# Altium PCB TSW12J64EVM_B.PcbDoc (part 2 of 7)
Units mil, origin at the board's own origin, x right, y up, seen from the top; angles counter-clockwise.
Board outline 8833 x 2680 mil, 10 copper layers (Top Layer L1, Gnd-Plane - L2, Signals - L3, Gnd-Plane - L4, Pwr Plane - L5, Signals - L6, Gnd-Plane - L7, Signals - L8, Gnd-Plane - L9, Bottom Layer - L10), stack 57.8 mil thick; 950 components, 533 nets, 2888 pads, 1732 vias.
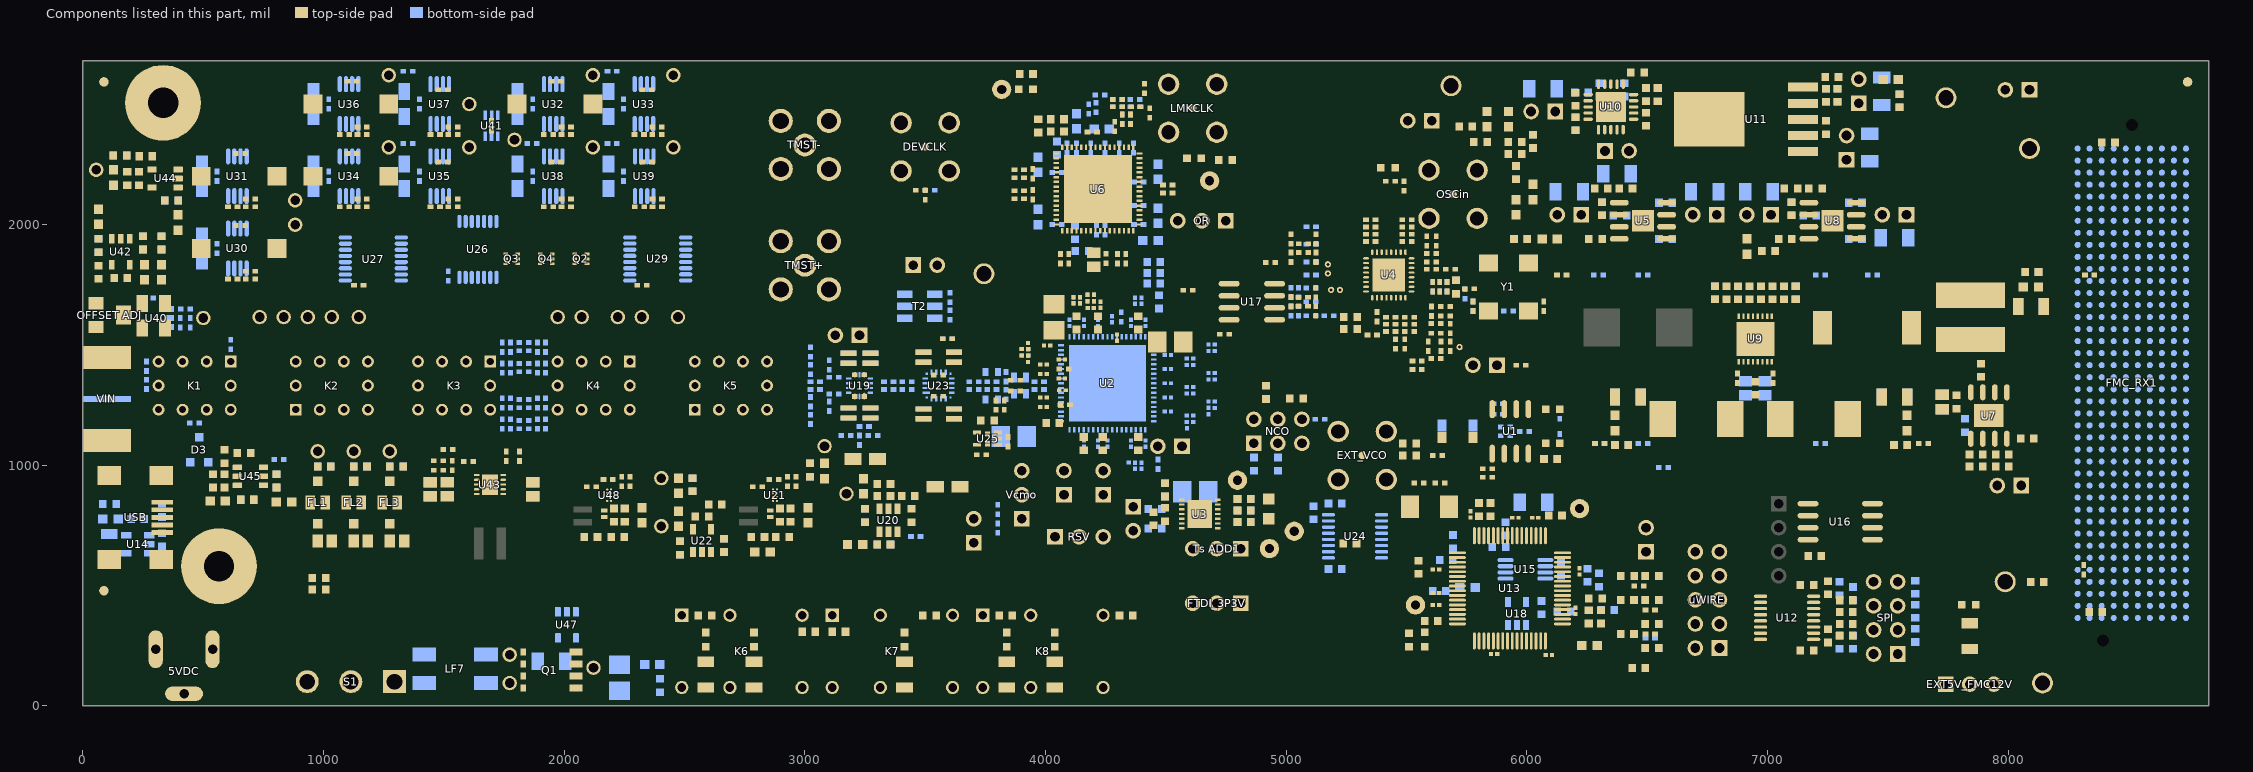
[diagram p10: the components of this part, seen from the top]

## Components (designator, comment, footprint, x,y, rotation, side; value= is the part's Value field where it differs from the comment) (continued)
R85 "CRCW06032K49FKEA" 0603L#1 6202.68,2520 r270 top
R86 "CRCW06035K90FKEA" 0603L#1 7069,1716 r270 top
R87 "CRCW06035K90FKEA" 0603L#1 6829,1716 r270 top
R88 "CRCW06034K99FKEA" 0603L#1 6226.68,2547.56 r180 bottom
R89 "CRCW06032K80FKEA" 0603L#1 6404.36,2558.87 r90 bottom
R90 "RC0603FR-07402RL" 0603L#1 6494.68,2539 r90 bottom
R91 "CRCW04024K99FKED" 0402L#1 5681.98,1567 r270 top
R92 "CSNL1206FT2L00" 1206 7474.44,2552.93 r90 bottom
R93 "RC0603FR-071KL" 0603L#1 7243,2536.39 r270 bottom
R94 "CRCW12061K00JNEA" 1206L 7840,289 r270 top
R95 "CSNL1206FT2L00" 1206 7423.44,2319.07 r90 bottom
R96 "RC0603FR-07357RL" 0603L#1 7267,2612 r180 top
R97 "CRCW060312K4FKEA" 0603L#1 6520,540 r0 top
R98 "CRCW060312K4FKEA" 0603L#1 6520,440 r0 top
R99 "ERJ-3GEY0R00V" 0603L#1 4455,737 r0 bottom
R100 "ERJ-3GEY0R00V" 0603L#1 4455,817 r0 bottom
R101 "CRCW060312K4FKEA" 0603L#1 6520,340 r0 top
R102 "CRCW060312K4FKEA" 0603L#1 6520,240 r0 top
R103 "CRCW06030000Z0EA" 0603L#1 329.24,811.96 r270 bottom
R104 "CRCW040224K0JNED" 0402L#1 6512.13,398 r180 top
R105 "CRCW060310K0FKEA" 0603L#1 5911.32,735 r90 bottom
R106 "CRCW060310K0FKEA" 0603L#1 5848.2,815 r90 top
R107 "CRCW060310K0FKEA" 0603L#1 5800.2,815 r90 top
R108 "RC0603JR-072K2L" 0603L#1 5883.76,659 r0 bottom
R109 "CRCW0603100RJNEA" 0603L#1 7327,438.5 r180 top
R110 "CRCW0603100RJNEA" 0603L#1 7327,340.5 r180 top
R111 "CRCW0603100RJNEA" 0603L#1 7327,389.5 r180 top
R112 "CRCW0603270RJNEA" 0603L#1 5510.91,273.24 r270 top
R113 "CRCW0603100RJNEA" 0603L#1 6418,540 r180 top
R114 "CRCW0603100RJNEA" 0603L#1 6417.44,298 r180 top
R115 "CRCW0603100RJNEA" 0603L#1 6464.88,157.56 r180 top
R116 "CRCW040224K0JNED" 0402L#1 6465.24,498 r180 top
R117 "CRCW0603100RJNEA" 0603L#1 6154.26,392.13 r180 bottom
R118 "CRCW0603100RJNEA" 0603L#1 7327,291.5 r180 top
R119 "CRCW0603100RJNEA" 0603L#1 6520,540 r0 bottom
R120 "CRCW0603100RJNEA" 0603L#1 6520,340 r0 bottom
R121 "CRCW0603100RJNEA" 0603L#1 6520,240 r0 bottom
R122 "RC0603JR-071K3L" 0603L#1 4122.93,1966.24 r270 bottom
R123 "CRCW060310K0FKEA" 0603L#1 7251,290.53 r270 top
R124 "CRCW0603100RJNEA" 0603L#1 6257,369.57 r270 top
R125 "CRCW0603100RJNEA" 0603L#1 6308.56,369.57 r270 top
R126 "CRCW0603100RJNEA" 0603L#1 6285,445 r0 top
R127 "CRCW0603100RJNEA" 0603L#1 6336.12,397.13 r0 bottom
R128 "CRCW040224K0JNED" 0402L#1 6512.13,298 r180 top
R129 "CRCW040224K0JNED" 0402L#1 6512.13,282 r180 bottom
R130 "CRCW060310K0FKEA" 0603L#1 6300,522.46 r270 bottom
R131 "CRCW060310K0FKEA" 0603L#1 6251,542.15 r270 bottom
R132 "CRCW06030000Z0EA" 0603L#1 8120,515 r0 top
R133 "CRCW04021K00FKED" 0402L#1 5923.24,1640 r180 bottom
R134 "RC0603JR-071KL" 0603L#1 4450,1754 r180 bottom
R135 "CRCW06032K10FKEA" 0603L#1 4470.64,1678.24 r90 bottom
R136 "CRCW06034K70JNEA" 0603L#1 4915.5,1302 r90 top
R137 "CRCW06034K70JNEA" 0603L#1 5043.06,1276 r0 top
R138 "CRCW06034K70JNEA" 0603L#1 5512.5,1040 r0 top
R139 "CRCW06032K00JNEA" 0603L#1 7613.44,292.56 r270 bottom
R140 "CRCW06032K00JNEA" 0603L#1 7613.44,392.56 r270 bottom
R141 "CRCW06032K00JNEA" 0603L#1 7613.44,492.56 r270 bottom
R142 "ERJ-3GEY0R00V" 0603L#1 4450,1843 r180 bottom
R143 "ERJ-3GEY0R00V" 0603L#1 4450,1798.5 r180 bottom
R144 "CRCW040210K0FKED" 0402L#5 5622.92,1588 r0 top
R145 "ERJ-2GE0R00X" 0402L#6 5603.24,1639 r270 top
R146 "ERJ-2GE0R00X" 0402L#1 5544,1432.5 r0 top
R147 "ERJ-2GE0R00X" 0402L#1 5544,1397.5 r180 top
R148 "ERJ-2GE0R00X" 0402L#6 5642.61,1494 r270 top
R149 "ERJ-2GE0R00X" 0402L#5 5590.24,1494 r90 top
R150 "CRCW04021M00JNED" 0402L#1 5681.98,1494 r90 top
R151 "CRCW06030000Z0EA" 0603L#1 5267,1615 r0 top
R152 "CRCW06030000Z0EA" 0603L#1 5267,1565 r180 top
R153 "CRCW040249R9FKED" 0402L#1 5357.34,1540 r0 top
R154 "CRCW0402261RFKED" 0402L#1 5489,2159.68 r270 top
R156 "CRCW0402127RFKED" 0402L#1 4372.35,2519 r0 bottom
R157 "CRCW0402127RFKED" 0402L#1 4298.98,2519 r180 bottom
R158 "CRCW040282R5FKED" 0402L#1 4372.35,2489 r180 bottom
R159 "CRCW040282R5FKED" 0402L#1 4298.98,2489 r0 bottom
R160 "CRCW04020000Z0ED" 0402L#1 3890.78,2193.37 r180 top
R161 "CRCW04020000Z0ED" 0402L#1 3890.78,2227.37 r180 top
R162 "CRCW0402107RFKED" 0402L#7 5020.05,1678.5 r270 top
R163 "CRCW04022K20JNED" 0402L#1 5051.36,1640.5 r270 bottom
R164 "CRCW04022K20JNED" 0402L#1 5051.36,1716.5 r90 bottom
R165 "CRCW040251R0JNED" 0402L#1 3480.37,2141.68 r0 top
R166 "CRCW0402560RJNED" 0402L#1 3947.24,2123 r270 top
R167 "CRCW0402560RJNED" 0402L#1 3947.24,2210.37 r270 top
R168 "CRCW0402365RFKED" 0402L#1 3024.02,1190 r90 bottom
R169 "CRCW040222R6FKED" 0402L#1 3043.7,1345.84 r180 bottom
R170 "CRCW04021K00FKED" 0402L#1 3461.05,702.97 r180 bottom
R171 "RC0603FR-0762KL" 0603L#1 3328.3,872 r0 top
R172 "CRCW060330K1FKEA" 0603L#1 3430,872 r180 top
R173 "CRCW04021K00FKED" 0402L#1 2802.99,910.02 r0 top
R174 "CRCW0402274KFKED" 0402L#1 2927.99,932.02 r270 top
R175 "CRCW0402100KFKED" 0402L#1 2871.99,940.02 r0 top
R176 "CRCW06035K23FKEA" 0603L#1 2573,787 r180 top
R177 "RC0603FR-0795K3L" 0603L#1 2628.12,836 r180 top
R178 "CRCW04020000Z0ED" 0402L#1 3227.22,1103 r90 bottom
R179 "CRCW04024R99FKED" 0402L#1 3974.32,1314.47 r0 bottom
R180 "CRCW04024R99FKED" 0402L#1 3974.32,1345.84 r0 bottom
R181 "CRCW04020000Z0ED" 0402L#1 3592.3,1525 r180 top
R182 "CRCW04022K00FKED" 0402L#1 3801.78,816 r270 bottom
R183 "CRCW04022K00FKED" 0402L#1 3801.78,738 r90 bottom
R184 "CRCW04021K21FKED" 0402L#1 3875.1,1307.55 r180 top
R185 "CRCW04021K21FKED" 0402L#1 3875.1,1352.76 r0 top
R186 "CRCW0603100RJNEA" 0603L#1 5203.13,568 r180 bottom
R187 "CRCW060310K0FKEA" 0603L#1 5264.44,673.35 r0 top
R188 "CRCW04022K00FKED" 0402L#1 3283.61,1122.68 r0 bottom
R189 "CRCW04022K00FKED" 0402L#1 3170.83,1122.68 r0 bottom
R190 "CRCW040210K0FKED" 0402L#1 3794.43,1249 r90 top
R191 "ERA-2AEB151X" 0402L#1 1777,1170.84 r270 bottom
R192 "1-1879213-6" 0402L#1 1833,1151.16 r0 bottom
R193 "ERA-2AEB151X" 0402L#1 1889,1170.84 r270 bottom
R194 "ERA-2AEB750X" 0402L#1 1777,1257.65 r270 bottom
R195 "ERA-2AEB1210X" 0402L#1 1833,1237.97 r0 bottom
R196 "ERA-2AEB750X" 0402L#1 1889,1257.65 r270 bottom
R197 "ERA-2AEB750X" 0402L#1 1777,1402.66 r270 bottom
R198 "ERA-2AEB1210X" 0402L#1 1833,1422.34 r0 bottom
R199 "ERA-2AEB750X" 0402L#1 1889,1402.66 r270 bottom
R200 "ERA-2AEB151X" 0402L#1 1777,1489.47 r90 bottom
R201 "1-1879213-6" 0402L#1 1833,1509.16 r0 bottom
R202 "ERA-2AEB151X" 0402L#1 1889,1489.47 r90 bottom
R203 "CRCW040222R6FKED" 0402L#1 3043.7,1314.47 r0 bottom
R204 "CRCW0402365RFKED" 0402L#1 3024.02,1470.31 r270 bottom
R205 "CRCW040215R0FKED" 0402L#1 3348.4,1314.47 r0 bottom
R206 "CRCW040215R0FKED" 0402L#1 3348.4,1345.84 r0 bottom
R207 "CRCW04020000Z0ED" 0402L#1 3424.86,1314.47 r0 bottom
R208 "CRCW04020000Z0ED" 0402L#1 3424.86,1345.84 r180 bottom
R209 "CRCW0402127RFKED" 0402L#1 3121.54,1295.71 r180 bottom
R210 "CRCW0402127RFKED" 0402L#1 3121.54,1364.61 r180 bottom
R211 "CRCW040240R2FKED" 0402L#1 3703.32,1314.47 r0 bottom
R212 "CRCW040240R2FKED" 0402L#1 3703.32,1345.84 r0 bottom
R213 "CRCW0402100KFKED" 0402L#1 623.44,1773.13 r0 top
R214 "CRCW0402100KFKED" 0402L#1 623.44,2073.13 r0 top
R215 "CRCW0402100KFKED" 0402L#1 1935.44,2373.13 r0 top
R216 "CRCW0402100KFKED" 0402L#1 2312.44,2373.13 r0 top
R217 "CRCW0402100KFKED" 0402L#1 1087.44,2073.13 r0 top
R218 "CRCW0402100KFKED" 0402L#1 1464.44,2073.13 r0 top
R219 "CRCW0402100KFKED" 0402L#1 1087.44,2373.13 r0 top
R220 "CRCW0402100KFKED" 0402L#1 1464.44,2373.13 r0 top
R221 "CRCW0402100KFKED" 0402L#1 1935.44,2073.13 r0 top
R222 "CRCW0402100KFKED" 0402L#1 2313.44,2073.13 r0 top
R224 "CRCW040210K0FKED" 0402L#1 2344.43,2559 r0 top
R225 "CRCW040210K0FKED" 0402L#1 1496.43,2259 r0 top
R226 "CRCW040210K0FKED" 0402L#1 1496.43,2559 r0 top
R227 "CRCW040210K0FKED" 0402L#1 1967.43,2259 r0 top
R228 "CRCW040210K0FKED" 0402L#1 2345.43,2259 r0 top
R229 "CRCW040249R9FKED" 0402L#1 615,1501 r270 bottom
R230 "CRCW040249R9FKED" 0402L#1 265,1410.47 r90 bottom
R231 "CRCW060360K4FKEA" 0603L#1 158,1778.11 r0 top
R232 "RC0603FR-0739K2L" 0603L#1 66,1800.96 r270 top
R233 "ERJ-2GE0R00X" 0402L#1 427,1648.4 r0 bottom
R234 "CRCW040210K0FKED" 0402L#1 655.43,1995 r0 top
R235 "CRCW040210K0FKED" 0402L#1 1967.43,2595 r0 top
R236 "CRCW040210K0FKED" 0402L#1 655.43,2295 r0 top
R237 "CRCW040210K0FKED" 0402L#1 1119.43,2295 r0 top
R238 "CRCW040210K0FKED" 0402L#1 1119.43,2595 r0 top
R239 "Used in BOM report" 0402L#1 3759.12,1109 r270 top
R240 "Used in BOM report" 0402L#1 3101.86,1244.31 r90 bottom
R241 "Used in BOM report" 0402L#1 3101.86,1416 r90 bottom
R242 "CRCW04021K00FKED" 0402L#1 1815,1037 r270 top
R243 "CRCW04021M00JNED" 0402L#1 1759.32,1037 r270 top
R244 "CRCW0402110KFKED" 0402L#1 1535,998.68 r270 top
R245 "CRCW04021M00JNED" 0402L#1 1478,979 r180 top
R246 "CRCW060380K6FKEA" 0603L#1 234.11,2191 r270 top
R247 "RC0603FR-0725K5L" 0603L#1 261.67,2283 r180 top
R248 "RC0603FR-0743K2L" 0603L#1 589.11,934.3 r90 top
R249 "CRCW060330K1FKEA" 0603L#1 589.11,1036 r270 top
R250 "CRCW04021K00FKED" 0402L#1 815.89,1023.03 r180 bottom
R251 "CRCW12061K00JNEA" 1206L 2589,129.15 r90 top
R252 "CRCW12061K00JNEA" 1206L 2789,129.15 r270 top
R253 "CRCW12061K00JNEA" 1206L 3414,129.15 r90 top
R254 "CRCW12061K00JNEA" 1206L 3839,129.15 r90 top
R255 "CRCW12061K00JNEA" 1206L 4039,129.15 r270 top
R256 "CRCW04021K00FKED" 0402L#1 2113.99,910.02 r0 top
R257 "CRCW0402274KFKED" 0402L#1 2238.99,932.02 r270 top
R258 "CRCW0402100KFKED" 0402L#1 2182.99,940.02 r0 top
R259 "ERJ-3GEY0R00V" 0603L#1 4335,376 r180 top
R260 "ERJ-3GEY0R00V" 0603L#1 3835,376 r180 top
R261 "ERJ-3GEY0R00V" 0603L#1 3141.56,307.56 r180 top
R262 "ERJ-3GEY0R00V" 0603L#1 3518,376 r0 top
R263 "ERJ-3GEY0R00V" 0603L#1 2585,376 r180 top
R264 "ERJ-3GEY0R00V" 0603L#1 3016.56,307.56 r180 top
RR6 "CRCW06034K99FKEA" 0603L#1 8415.56,2340 r180 top
RR7 "ERJ-3GEY0R00V" 0603L#1 8363,390 r180 top
RSV "TSW-103-07-G-S" TSW-103-07-G-S 4139.28,702 r0 top
S1 "L101011MS02Q" "SW_ L101011MS02Q" 1114,212.6 r270 top
SH-1V2ADC_INT_1_2 "SNT-100-BK-G" SNT-100-BK-G 6374.27,2305 r180 top
SH-1V2ADC_LDO_1_2 "SNT-100-BK-G" SNT-100-BK-G 6067.27,2469 r180 top
SH-1V9ADC_1_2 "SNT-100-BK-G" SNT-100-BK-G 7379,2552.93 r90 top
SH-1V9INT_1_2 "SNT-100-BK-G" SNT-100-BK-G 7328,2319.07 r90 top
SH-EXT5V_FMC12V_1_2 "SNT-100-BK-G" SNT-100-BK-G 7790,90 r180 top
SH-FTDI_3P3V_1_2 "SNT-100-BK-G" SNT-100-BK-G 4761.28,426 r0 top
SH-J2_1_2 "SNT-100-BK-G" SNT-100-BK-G 5826,1415 r180 top
SH-LMK_INT_1_2 "SNT-100-BK-G" SNT-100-BK-G 6739,2040 r180 top
SH-LMK_LDO_1_2 "SNT-100-BK-G" SNT-100-BK-G 6176,2040 r180 top
SH-LMX_INT_1_2 "SNT-100-BK-G" SNT-100-BK-G 7527,2040 r180 top
SH-LMX_LDO_1_2 "SNT-100-BK-G" SNT-100-BK-G 6964,2040 r180 top
SH-RSV_1_2 "SNT-100-BK-G" SNT-100-BK-G 4089.28,702 r0 top
"SH-Ts ADD1_1_2" "SNT-100-BK-G" SNT-100-BK-G 4761.28,653 r180 top
SPI "TSW-104-07-G-D" TSW-104-07-G-D 7490,365 r90 top
Status1 "LTST-C190GKT" LED_LTST-C190 4617.5,2274.95 r0 top
Status2 "LTST-C190GKT" LED_LTST-C190 3918.53,2561 r0 top
T2 "TCM2-43X+" Mini-Circuits-DB1627 3477.65,1659.95 r270 bottom
TCRIT1 "TESTPOINT" TESTPOINT#1 4930.28,653 r270 top
TCRIT2 "TESTPOINT" TESTPOINT#1 5033.5,725 r270 top
TCRIT3 "TESTPOINT" TESTPOINT#1 4797.72,937 r270 top
Tdiode "TSW-102-07-G-S" TSW-102-07-G-S 4364.28,777 r270 top
TEMP "LTST-C170KRKT" LED_LTST-C170 4927.28,817.94 r270 top
TMST+ "142-0701-231" Johnson_142-0701-231 3000,1830.16 r270 top
TMST- "142-0701-231" Johnson_142-0701-231 3000,2330.16 r270 top
TP41_4 "TESTPOINT" TP_VIA_060RND040 1794,2351.4 r0 top
"Ts ADD1" "TSW-103-07-G-S" TSW-103-07-G-S 4711.28,653 r180 top
U1 "LMC6762AIMX/NOPB" M08A_L 5931,1140 r270 top
U2 "ADC12J4000NKE" RLY0068A 4257.39,1340 r0 bottom
U3 "LM95233CISD/NOPB" SDA14B 4640.28,796.76 r0 top
U4 "TRF3765IRHB" RHB0032E 5426.24,1790 r270 top
U5 "LP3878MR-ADJ/NOPB" MRA08A_N 6482,2015 r180 top
U6 "LMK04828BISQ/NOPB" NKD0064A 4217.56,2147 r90 top
U7 "TPS54327DDA" DDA0008B_L 7919,1206 r90 top
U8 "LP3878MR-ADJ/NOPB" MRA08A_N 7270,2015 r180 top
U9 "LM26400YSDE/NOPB" SDA16A 6949,1524 r270 top
U10 "TPS74901RGW" RGW0020A 6348.68,2488 r90 top
U11 "LP38513TJ-ADJ/NOPB" TJ5A_N 6911,2436 r180 top
U12 "SN74AVC4T774PW" PW0016A_L 7081,365.53 r0 top
U13 "FT4232HL" LQFP64_N 5929.47,488 r0 top
U14 "TLV70233DBV" DBV0005A_N#1 228.7,670.86 r180 bottom
U15 "93LC46B-I/MS" MSOP-MS8_N 5994,567 r0 bottom
U16 "24C65T/SM" SOIJ-SM8_N 7302,765 r180 top
U17 "MC10EP32D" 751-06_N 4857.33,1678.5 r180 top
U18 "SN74LVC1G125DBV" SOP-5_.95MM_(DBV) 5958.68,384.9 r90 bottom
U19 "LMH5401IRMSR" RMS0014A 3227.22,1330.16 r90 bottom
U20 "TPS79301DBVR" DBV0006A_N#1 3347,771 r90 top
U21 "LMR70503TM/NOPB" YFX0008ADAC 2875.99,875.02 r0 top
U22 "TPS72301DBVR" DBV0005A_N#1 2573,686 r90 top
U23 "LMH6401IRMZR" RMZ0016A 3555.88,1330.16 r0 bottom
U24 "SN74AVC4T774PW" PW0016A_L 5285.81,704 r180 bottom
U25 "OPA376AIDCKT" DCK0005A_N 3759.12,1110 r180 top
U26 "CD74HC14PW" PW0014A_N 1642,1896 r270 bottom
U27 "DRV777PWR" PW0016A_N 1207.28,1856 r180 bottom
U29 "DRV777PWR" PW0016A_N 2389.14,1856.43 r180 bottom
U30 "LMC555CMM/NOPB" MUA08A_N 642.63,1900 r270 bottom
U31 "LMC555CMM/NOPB" MUA08A_N 642.63,2200 r270 bottom
U32 "LMC555CMM/NOPB" MUA08A_N 1954.63,2500 r270 bottom
U33 "LMC555CMM/NOPB" MUA08A_N 2331.63,2500 r270 bottom
U34 "LMC555CMM/NOPB" MUA08A_N 1106.63,2200 r270 bottom
U35 "LMC555CMM/NOPB" MUA08A_N 1483.63,2200 r270 bottom
U36 "LMC555CMM/NOPB" MUA08A_N 1106.63,2500 r270 bottom
U37 "LMC555CMM/NOPB" MUA08A_N 1483.63,2500 r270 bottom
U38 "LMC555CMM/NOPB" MUA08A_N 1954.63,2200 r270 bottom
U39 "LMC555CMM/NOPB" MUA08A_N 2332.63,2200 r270 bottom
U40 "LMH6559MFX/NOPB" DBV0005A_N#2 306.46,1611 r180 bottom
U41 "SN74LVC1G57DCK" DCK-6 1698.48,2410 r0 bottom
U42 "TPS72301DBVR" DBV0005A_N#2 158,1886 r270 top
U43 "TPS63060DSC" DSC0010E 1692,919 r180 top
U44 "TPS73201DBVR" DBV0005A_N#2 342,2191 r180 top
U45 "TPS79301DBVR" DBV0006A_N#2 697,953 r180 top
U47 "TPS2400DBVR" DBV0005A_N#2 2011.9,336.42 r270 bottom
U48 "LMR70503TM/NOPB" YFX0008ADAC 2186.99,875.02 r0 top
USB "651-305-142-821" CONN_USB-MINI-AB-651-305-142-821 220.47,782.44 r270 top
USB_PWR "LTST-C190GKT" LED_LTST-C190 5574.91,275.2 r270 top
uWIRE "N2510-6002-RB" CONN_2510-6002 6750,440 r90 top
VA12 "TSW-102-07-G-S" TSW-102-07-G-S 5555,2431 r180 top
VA19 "TSW-102-07-G-S" TSW-102-07-G-S 4239.28,927 r90 top
VADJ_RX "5011" Keystone5011 8088,2315 r90 top
Vbg "TSW-102-07-G-S" TSW-102-07-G-S 4076.78,927 r90 top
Vcmo "TSW-103-07-G-S" TSW-103-07-G-S 3901.78,877 r90 top
Vcmo_2_3 "SNT-100-BK-G" SNT-100-BK-G 3901.78,927 r90 top
VD12 "TSW-102-07-G-S" TSW-102-07-G-S 4517,1078 r180 top
VIN "142-0701-806" Johnson_142-0701-80x_NoVias 100,1275 r270 bottom
VIO_3P75_U19 "TESTPOINT" TP_VIA_060RND040 3082.01,1079 r0 top
VIO_3P75_U23 "TESTPOINT" TP_VIA_060RND040 3173,880.98 r90 top
VIO_5V_DRV "TESTPOINT" TP_VIA_060RND040 1126,1057 r180 top
VIO_5V_LMC "TESTPOINT" TP_VIA_060RND040 976,1057 r180 top
VIO_5V_LMH "TESTPOINT" TP_VIA_060RND040 55.99,2226.43 r270 top
VIO_5V_LOGIC "TESTPOINT" TP_VIA_060RND040 1276,1057 r180 top
VIO_-1P25_U19 "TESTPOINT" TP_VIA_060RND040 2404,946.02 r90 top
VIO_-1P25_U23 "TESTPOINT" TP_VIA_060RND040 2404,745.98 r90 top
Vtune "TESTPOINT" TESTPOINT#3 5720.24,1513.68 r180 top
Y1 "CWX813-100.0M" OSC_CWX 5923.24,1740 r180 top
Y2 "ABM3-12.000MHZ-B2-T" XTAL_ABM3 5595.47,827 r180 top
ZZ2 "These assemblies are ESD sensitive, ESD precautions shall be observed." AssemblyNote 209,3829.11 r0 top
ZZ3 "These assemblies must be clean and free from flux and all contaminants. Use of no clean flux is not acceptable." AssemblyNote 209,3740.56 r0 top
ZZ4 "These assemblies must comply with workmanship standards IPC-A-610 Class 2., unless otherwise specified." AssemblyNote 209,3652 r0 top

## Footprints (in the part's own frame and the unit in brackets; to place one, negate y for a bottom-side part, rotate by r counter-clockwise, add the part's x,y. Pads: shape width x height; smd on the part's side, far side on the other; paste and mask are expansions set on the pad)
0201#1 [mm] "Data from Kemet datasheet CC101_COM dated 7/28/11"
  rect 0.46x0.42 smd mask+0.048: 1(-0.33,0) 2(0.33,0)
  body extent -0.31,-0.16 0.31,0.16, height 0.26
0201#2 [mm] "Data from Kemet datasheet CC101_COM dated 7/28/11"
  rect 0.42x0.46 smd mask+0.048: 1(-0.33,0)
  rect 0.46x0.42 smd mask+0.048: 2(0.33,0)
  body extent -0.31,-0.16 0.31,0.16, height 0.26
0306 [mil] "bxl footprint"
  rect 22x67 smd: 1(-20.5,0) 2(20.5,0)
  body extent -17,-33 17,33, height 24
0402L#1 [mm] "0402 from SM-752 data"
  rect 0.6x0.5 smd: 1(-0.5,0) 2(0.5,0)
  body extent -0.55,-0.3 0.55,0.3, height 0.6
0402L#2 [mm] "0402 from SM-752 data"
  rect 0.6x0.5 smd mask+0.071: 1(-0.5,0) 2(0.5,0)
  body extent -0.55,-0.3 0.55,0.3, height 0.6
0402L#3 [mm] "0402 from SM-752 data"
  rect 0.6x0.5 smd: 1(-0.5,0)
  rect 0.6x0.5 smd mask+0.075: 2(0.5,0)
  body extent -0.55,-0.3 0.55,0.3, height 0.6
0402L#4 [mm] "0402 from SM-752 data"
  rect 0.6x0.5 smd: 1(-0.5,0)
  rect 0.6x0.5 smd mask+0.053: 2(0.5,0)
  body extent -0.55,-0.3 0.55,0.3, height 0.6
0402L#5 [mm] "0402 from SM-752 data"
  rect 0.6x0.5 smd mask+0.071: 1(-0.5,0)
  rect 0.6x0.5 smd: 2(0.5,0)
  body extent -0.55,-0.3 0.55,0.3, height 0.6
0402L#6 [mm] "0402 from SM-752 data"
  rect 0.6x0.5 smd: 1(-0.5,0)
  rect 0.6x0.5 smd mask+0.071: 2(0.5,0)
  body extent -0.55,-0.3 0.55,0.3, height 0.6
0402L#7 [mm] "0402 from SM-752 data"
  rect 0.6x0.5 smd mask+0.066: 1(-0.5,0) 2(0.5,0)
  body extent -0.55,-0.3 0.55,0.3, height 0.6
0603 [mm] "0603 from SM-752 data"
  rect 1x0.95 smd: 1(-0.8,0) 2(0.8,0)
  silkscreen extent -1.52,-0.69 1.52,0.69, body extent -0.87,-0.47 0.87,0.47, height 0.85
0603HC [mm] "SMD, 2-Leads, Body 1.8x1.12mm, Lead Spacing 1.28mm"
  rect 0.64x1.02 smd: 1(-0.64,0) 2(0.64,0)
  silkscreen extent -0.18,-0.7 0.18,0.7, body extent -0.9,-0.56 0.9,0.56, height 1.01
0603L#1 [mm] "0603 from SM-752 data"
  rect 0.8x0.85 smd: 1(-0.7,0) 2(0.7,0)
  silkscreen extent -0.07,-0.33 0.07,0.33, body extent -0.87,-0.47 0.87,0.47, height 0.85
0603L#2 [mm] "0603 from SM-752 data"
  rect 0.8x0.85 smd: 1(-0.7,0)
  rect 0.8x0.85 smd mask+0.053: 2(0.7,0)
  silkscreen extent -0.07,-0.33 0.07,0.33, body extent -0.87,-0.47 0.87,0.47, height 0.85
0603L#3 [mm] "0603 from SM-752 data"
  rect 0.8x0.85 smd: 1(-0.7,0)
  rect 0.8x0.85 smd mask+0.064: 2(0.7,0)
  silkscreen extent -0.07,-0.33 0.07,0.33, body extent -0.87,-0.47 0.87,0.47, height 0.85
751-06_N [mm] "SOIC, 8-Leads, Body 4.9x3.9mm, Pitch 1.27mm, IPC Medium Density"
  oval 2.2x0.6 smd: 1(-2.4,1.905) 2(-2.4,0.635) 3(-2.4,-0.635) 4(-2.4,-1.905) 5(2.4,-1.905) 6(2.4,-0.635) 7(2.4,0.635) 8(2.4,1.905)
  silkscreen extent -2.53,-2.5 0.9,2.88, body extent -1.95,-2.45 1.95,2.45, height 1.75
0805L [mm] "0805 from SM-752 data"
  rect 1.1x1.4 smd: 1(-0.75,0) 2(0.75,0)
  body extent -1.1,-0.72 1.1,0.72, height 1.1
1206 [mm] "1206 from SM-752 data"
  rect 1.3x1.85 smd: 1(-1.45,0) 2(1.45,0)
  silkscreen extent -2.4,-1.21 2.4,1.21, body extent -1.7,-0.9 1.7,0.9, height 1.35
1206L [mm] "1206 from SM-752 data"
  rect 1.1x1.75 smd: 1(-1.35,0) 2(1.35,0)
  silkscreen extent -0.4,-0.78 0.4,0.77, body extent -1.7,-0.9 1.7,0.9, height 1.35
3216-18 [mm] "Medium density IPC, based on Kemet T495 dimensions"
  rect 1.8x1.25 smd: 1(-1.3,0) 2(1.3,0)
  silkscreen extent -2.49,-0.54 -2.49,0.54, body extent -1.7,-0.9 1.7,0.9, height 1.8
3528-21#1 [mm] "Medium Density IPC, based on SM-782 section 8.4"
  rect 1.95x2.25 smd: 1(-1.375,0) 2(1.375,0)
  silkscreen extent -2.66,-1.5 1.9,1.79, body extent -1.85,-1.5 1.85,1.5, height 2.1
3528-21#2 [mm] "Medium Density IPC, based on SM-782 section 8.4"
  rect 1.95x2.25 smd: 1(-2.14,-0.025) 2(0.61,-0.025)
  silkscreen extent -3.05,-1.53 0,1.47, body extent -2.62,-1.53 1.08,1.47, height 2.1
AssemblyNote [mil] "Assembly Note"
CDRH6D28 [mm] "Sumida reommended land pattern"
  rect 2.65x7.3 smd: 1(-2.325,0) 2(2.325,0)
  silkscreen extent -4,-4 4,4, body extent -3.5,-3.5 3.5,3.5, height 3
CONN_2510-6002 [mm] "3M 2500 series TS-0770-L December 15, 2011"
  rect 1.65x1.65 hole 1.016 mask+0: 1(-5.08,-1.27)
  round 1.65 hole 1.016 mask+0: 2(-5.08,1.27) 3(-2.54,-1.27) 4(-2.54,1.27) 5(0,-1.27) 6(0,1.27) 7(2.54,-1.27) 8(2.54,1.27) 9(5.08,-1.27) 10(5.08,1.27)
  silkscreen extent -10.01,-4.17 10.01,4.47, body extent -10.01,-4.11 10.01,4.52, height 9.92
CONN_CUI-PJ-202AH [mm] "Conn_DC Jack"
  oval 1.5x4 hole 1 slot 3.5 at 90 deg: 1(0,0) 2(6,0)
  oval 4x1.5 hole 1 slot 3.5 at 0 deg: 3(3,4.7)
  silkscreen extent -0.7,-4.5 13.7,4.5, body extent -0.7,-4.5 13.7,4.9, height 11.02
CONN_LTI_SASF546-P26-X1 [mm]
  round 0.8 smd: 1(0,0)
  round 2.25 hole 1.5 mask+0.051: 2(-2.54,2.54) 3(-2.54,-2.54) 4(2.54,-2.54) 5(2.54,2.54)
  silkscreen extent -3.4,-3.4 3.4,3.4, body extent -3.17,-3.17 3.17,3.17, height 12.53
CONN_SEARAY_ASP-134488-01 [mm]
  round 0.635 hole 1.27 unplated mask+0.572: 401(27.191,0) 402(-27.191,-3.048)
  round 0.64 smd paste+0.125 mask+0.05: A1(24.716,5.715) A2(23.446,5.715) A3(22.176,5.715) A4(20.906,5.715) A5(19.636,5.715) A6(18.366,5.715) A7(17.096,5.715) A8(15.826,5.715) A9(14.556,5.715) A10(13.286,5.715) A11(12.016,5.715) A12(10.746,5.715) A13(9.476,5.715) A14(8.206,5.715) A15(6.936,5.715) A16(5.666,5.715) A17(4.396,5.715) A18(3.126,5.715) A19(1.856,5.715) A20(0.586,5.715) A21(-0.684,5.715) A22(-1.954,5.715) A23(-3.224,5.715) A24(-4.494,5.715) A25(-5.764,5.715) A26(-7.034,5.715) A27(-8.304,5.715) A28(-9.574,5.715) A29(-10.844,5.715) A30(-12.114,5.715) A31(-13.384,5.715) A32(-14.654,5.715) A33(-15.924,5.715) A34(-17.194,5.715) A35(-18.464,5.715) A36(-19.734,5.715) A37(-21.004,5.715) A38(-22.274,5.715) A39(-23.544,5.715) A40(-24.814,5.715) B1(24.716,4.445) B2(23.446,4.445) B3(22.176,4.445) B4(20.906,4.445) B5(19.636,4.445) B6(18.366,4.445) B7(17.096,4.445) B8(15.826,4.445) B9(14.556,4.445) B10(13.286,4.445) B11(12.016,4.445) B12(10.746,4.445) B13(9.476,4.445) B14(8.206,4.445) B15(6.936,4.445) B16(5.666,4.445) B17(4.396,4.445) B18(3.126,4.445) B19(1.856,4.445) B20(0.586,4.445) B21(-0.684,4.445) B22(-1.954,4.445) B23(-3.224,4.445) B24(-4.494,4.445) B25(-5.764,4.445) B26(-7.034,4.445) B27(-8.304,4.445) B28(-9.574,4.445) B29(-10.844,4.445) B30(-12.114,4.445) B31(-13.384,4.445) B32(-14.654,4.445) B33(-15.924,4.445) B34(-17.194,4.445) B35(-18.464,4.445) B36(-19.734,4.445) B37(-21.004,4.445) B38(-22.274,4.445) B39(-23.544,4.445) B40(-24.814,4.445) C1(24.716,3.175) C2(23.446,3.175) C3(22.176,3.175) C4(20.906,3.175) C5(19.636,3.175) C6(18.366,3.175) C7(17.096,3.175) C8(15.826,3.175) C9(14.556,3.175) C10(13.286,3.175) C11(12.016,3.175) C12(10.746,3.175) C13(9.476,3.175) C14(8.206,3.175) C15(6.936,3.175) C16(5.666,3.175) C17(4.396,3.175) C18(3.126,3.175) C19(1.856,3.175) C20(0.586,3.175) C21(-0.684,3.175) C22(-1.954,3.175) C23(-3.224,3.175) C24(-4.494,3.175) C25(-5.764,3.175) C26(-7.034,3.175) C27(-8.304,3.175) C28(-9.574,3.175) C29(-10.844,3.175) C30(-12.114,3.175) C31(-13.384,3.175) C32(-14.654,3.175) C33(-15.924,3.175) C34(-17.194,3.175) C35(-18.464,3.175) C36(-19.734,3.175) C37(-21.004,3.175) C38(-22.274,3.175) C39(-23.544,3.175) C40(-24.814,3.175) D1(24.716,1.905) D2(23.446,1.905) D3(22.176,1.905) D4(20.906,1.905) D5(19.636,1.905) D6(18.366,1.905) D7(17.096,1.905) D8(15.826,1.905) D9(14.556,1.905) D10(13.286,1.905) D11(12.016,1.905) D12(10.746,1.905) D13(9.476,1.905) D14(8.206,1.905) D15(6.936,1.905) D16(5.666,1.905) D17(4.396,1.905) D18(3.126,1.905) D19(1.856,1.905) D20(0.586,1.905) D21(-0.684,1.905) D22(-1.954,1.905) D23(-3.224,1.905) D24(-4.494,1.905) D25(-5.764,1.905) D26(-7.034,1.905) D27(-8.304,1.905) D28(-9.574,1.905) D29(-10.844,1.905) D30(-12.114,1.905) D31(-13.384,1.905) D32(-14.654,1.905) D33(-15.924,1.905) D34(-17.194,1.905) D35(-18.464,1.905) D36(-19.734,1.905) D37(-21.004,1.905) D38(-22.274,1.905) D39(-23.544,1.905) D40(-24.814,1.905) E1(24.716,0.635) E2(23.446,0.635) E3(22.176,0.635) E4(20.906,0.635) E5(19.636,0.635) E6(18.366,0.635) E7(17.096,0.635) E8(15.826,0.635) E9(14.556,0.635) E10(13.286,0.635) E11(12.016,0.635) E12(10.746,0.635) E13(9.476,0.635) E14(8.206,0.635) E15(6.936,0.635) E16(5.666,0.635) E17(4.396,0.635) E18(3.126,0.635) E19(1.856,0.635) E20(0.586,0.635) E21(-0.684,0.635) E22(-1.954,0.635) E23(-3.224,0.635) E24(-4.494,0.635) E25(-5.764,0.635) E26(-7.034,0.635) E27(-8.304,0.635) E28(-9.574,0.635) E29(-10.844,0.635) E30(-12.114,0.635) E31(-13.384,0.635) E32(-14.654,0.635) E33(-15.924,0.635) E34(-17.194,0.635) E35(-18.464,0.635) E36(-19.734,0.635) E37(-21.004,0.635) E38(-22.274,0.635) E39(-23.544,0.635) E40(-24.814,0.635) F1(24.716,-0.635) F2(23.446,-0.635) F3(22.176,-0.635) F4(20.906,-0.635) F5(19.636,-0.635) F6(18.366,-0.635) F7(17.096,-0.635) F8(15.826,-0.635) F9(14.556,-0.635) F10(13.286,-0.635) F11(12.016,-0.635) F12(10.746,-0.635) F13(9.476,-0.635) F14(8.206,-0.635) F15(6.936,-0.635) F16(5.666,-0.635) F17(4.396,-0.635) F18(3.126,-0.635) F19(1.856,-0.635) F20(0.586,-0.635) F21(-0.684,-0.635) F22(-1.954,-0.635) F23(-3.224,-0.635) F24(-4.494,-0.635) F25(-5.764,-0.635) F26(-7.034,-0.635) F27(-8.304,-0.635) F28(-9.574,-0.635) F29(-10.844,-0.635) F30(-12.114,-0.635) F31(-13.384,-0.635) F32(-14.654,-0.635) F33(-15.924,-0.635) F34(-17.194,-0.635) F35(-18.464,-0.635) F36(-19.734,-0.635) F37(-21.004,-0.635) F38(-22.274,-0.635) F39(-23.544,-0.635) F40(-24.814,-0.635) G1(24.716,-1.905) G2(23.446,-1.905) G3(22.176,-1.905) G4(20.906,-1.905) G5(19.636,-1.905) G6(18.366,-1.905) G7(17.096,-1.905) G8(15.826,-1.905) G9(14.556,-1.905) G10(13.286,-1.905) G11(12.016,-1.905) G12(10.746,-1.905) G13(9.476,-1.905) G14(8.206,-1.905) G15(6.936,-1.905) G16(5.666,-1.905) G17(4.396,-1.905) G18(3.126,-1.905) G19(1.856,-1.905) G20(0.586,-1.905) G21(-0.684,-1.905) G22(-1.954,-1.905) G23(-3.224,-1.905) G24(-4.494,-1.905) G25(-5.764,-1.905) G26(-7.034,-1.905) G27(-8.304,-1.905) G28(-9.574,-1.905) G29(-10.844,-1.905) G30(-12.114,-1.905) G31(-13.384,-1.905) G32(-14.654,-1.905) G33(-15.924,-1.905) G34(-17.194,-1.905) G35(-18.464,-1.905) G36(-19.734,-1.905) G37(-21.004,-1.905) G38(-22.274,-1.905) G39(-23.544,-1.905) G40(-24.814,-1.905) H1(24.716,-3.175) H2(23.446,-3.175) H3(22.176,-3.175) H4(20.906,-3.175) H5(19.636,-3.175) H6(18.366,-3.175) H7(17.096,-3.175) H8(15.826,-3.175) H9(14.556,-3.175) H10(13.286,-3.175) H11(12.016,-3.175) H12(10.746,-3.175) H13(9.476,-3.175) H14(8.206,-3.175) H15(6.936,-3.175) H16(5.666,-3.175) H17(4.396,-3.175) H18(3.126,-3.175) H19(1.856,-3.175) H20(0.586,-3.175) H21(-0.684,-3.175) H22(-1.954,-3.175) H23(-3.224,-3.175) H24(-4.494,-3.175) H25(-5.764,-3.175) H26(-7.034,-3.175) H27(-8.304,-3.175) H28(-9.574,-3.175) H29(-10.844,-3.175) H30(-12.114,-3.175) H31(-13.384,-3.175) H32(-14.654,-3.175) H33(-15.924,-3.175) H34(-17.194,-3.175) H35(-18.464,-3.175) H36(-19.734,-3.175) H37(-21.004,-3.175) H38(-22.274,-3.175) H39(-23.544,-3.175) H40(-24.814,-3.175) J1(24.716,-4.445) J2(23.446,-4.445) J3(22.176,-4.445) J4(20.906,-4.445) J5(19.636,-4.445) J6(18.366,-4.445) J7(17.096,-4.445) J8(15.826,-4.445) J9(14.556,-4.445) J10(13.286,-4.445) J11(12.016,-4.445) J12(10.746,-4.445) J13(9.476,-4.445) J14(8.206,-4.445) J15(6.936,-4.445) J16(5.666,-4.445) J17(4.396,-4.445) J18(3.126,-4.445) J19(1.856,-4.445) J20(0.586,-4.445) J21(-0.684,-4.445) J22(-1.954,-4.445) J23(-3.224,-4.445) J24(-4.494,-4.445) J25(-5.764,-4.445) J26(-7.034,-4.445) J27(-8.304,-4.445) J28(-9.574,-4.445) J29(-10.844,-4.445) J30(-12.114,-4.445) J31(-13.384,-4.445) J32(-14.654,-4.445) J33(-15.924,-4.445) J34(-17.194,-4.445) J35(-18.464,-4.445) J36(-19.734,-4.445) J37(-21.004,-4.445) J38(-22.274,-4.445) J39(-23.544,-4.445) J40(-24.814,-4.445) K1(24.716,-5.715) K2(23.446,-5.715) K3(22.176,-5.715) K4(20.906,-5.715) K5(19.636,-5.715) K6(18.366,-5.715) K7(17.096,-5.715) K8(15.826,-5.715) K9(14.556,-5.715) K10(13.286,-5.715) K11(12.016,-5.715) K12(10.746,-5.715) K13(9.476,-5.715) K14(8.206,-5.715) K15(6.936,-5.715) K16(5.666,-5.715) K17(4.396,-5.715) K18(3.126,-5.715) K19(1.856,-5.715) K20(0.586,-5.715) K21(-0.684,-5.715) K22(-1.954,-5.715) K23(-3.224,-5.715) K24(-4.494,-5.715) K25(-5.764,-5.715) K26(-7.034,-5.715) K27(-8.304,-5.715) K28(-9.574,-5.715) K29(-10.844,-5.715) K30(-12.114,-5.715) K31(-13.384,-5.715) K32(-14.654,-5.715) K33(-15.924,-5.715) K34(-17.194,-5.715) K35(-18.464,-5.715) K36(-19.734,-5.715) K37(-21.004,-5.715) K38(-22.274,-5.715) K39(-23.544,-5.715) K40(-24.814,-5.715)
  silkscreen extent -28.49,-8.18 29.69,8.18, body extent -27.89,-7.34 29.49,7.34, height 7.07
CONN_USB-MINI-AB-651-305-142-821 [mm] "WE-USB2-MINI-AB TYPE"
  rect 0.5x2.3 smd: 1(-1.6,2.8) 2(-0.8,2.8) 3(0,2.8) 4(0.8,2.8) 5(1.6,2.8)
  rect 2x2.5 smd: 6(4.45,2.7) 7(4.45,-2.8) 8(-4.45,-2.8) 9(-4.45,2.7)
  silkscreen extent -4.03,-5.6 4,1.1, body extent -4.95,-5.72 4.95,3.68, height 4.12
DBV0005A_N#1 [mm] "SOT23, 5-Leads, Body 2.9x1.6mm, Pitch 0.95mm, Lead Span 2.8mm, IPC Medium Density"
  rect 1.1x0.65 smd: 1(-1.2,0.95) 2(-1.2,0) 3(-1.2,-0.95) 4(1.2,-0.95) 5(1.2,0.95)
  silkscreen extent -1.33,-1.55 0.25,1.95, body extent -0.87,-1.52 0.87,1.53, height 1.45
DBV0005A_N#2 [mm] "SOT23, 5-Leads, Body 2.9x1.6mm, Pitch 0.95mm, Lead Span 2.8mm, IPC Medium Density"
  rrect17% 1x0.6 smd: 1(-1.375,0.95) 2(-1.375,0) 3(-1.375,-0.95) 4(1.375,-0.95) 5(1.375,0.95)
  silkscreen extent -1.63,-1.55 0.38,1.55, body extent -1.42,-1.46 1.42,1.46, height 1.09
DBV0006A_N#1 [mm] "SOT23, 6-Leads, Body 2.9x1.6mm, Pitch 0.95mm, Lead Span 2.8mm, IPC Medium Density"
  rect 1.1x0.65 smd: 1(-1.2,0.95) 2(-1.2,0) 3(-1.2,-0.95) 4(1.2,-0.95) 5(1.2,0) 6(1.2,0.95)
  silkscreen extent -1.32,-1.55 0.25,1.95, body extent -1.42,-1.46 1.42,1.46, height 1.11
DBV0006A_N#2 [mm] "SOT23, 6-Leads, Body 2.9x1.6mm, Pitch 0.95mm, Lead Span 2.8mm, IPC Medium Density"
  rrect17% 1x0.6 smd: 1(-1.375,0.95) 2(-1.375,0) 3(-1.375,-0.95) 4(1.375,-0.95) 5(1.375,0) 6(1.375,0.95)
  silkscreen extent -1.68,-1.55 0.5,1.55, body extent -1.42,-1.46 1.42,1.46, height 1.12
DCK0005A_N [mm] "SOT353, 5-Leads, Body 2x1.3mm, Pitch 0.65mm, Lead Span 2.1mm, IPC Medium Density"
  rrect25% 0.85x0.4 smd mask+0.074: 1(-1.125,0.65) 2(-1.125,0) 3(-1.125,-0.65)
  rrect25% 0.85x0.4 smd: 4(1.125,-0.65) 5(1.125,0.65)
  silkscreen extent -1.48,-1.02 0.55,1.1, body extent -1.14,-1 1.14,1, height 0.95
DCK-6 [mil]
  rect 15x38 smd: 1(-25.9,-43.4) 2(0.1,-43.4) 3(26.1,-43.4) 4(26.1,43.6) 5(-0.3,43.6) 6(-25.9,43.6)
DDA0008B_L [mm] "SOIC, 8-Leads, Body 4.9x3.9mm, Pitch 1.27mm, Exposed Pad, IPC High Density"
  oval 1.7x0.6 smd: 1(-2.45,1.905) 2(-2.45,0.635) 3(-2.45,-0.635) 4(-2.45,-1.905) 5(2.45,-1.905) 6(2.45,-0.635) 7(2.45,0.635) 8(2.45,1.905)
  rect 2.41x3.1 smd: 9(0,0)
  silkscreen extent -2.57,-2.5 1.2,2.88, body extent -2,-2.5 2,2.5, height 1.68
DSC0010E [mm]
  oval 0.6x0.24 smd mask+0.072: 1(-1.4,1) 2(-1.4,0.5) 3(-1.4,0) 4(-1.4,-0.5) 5(-1.4,-1) 6(1.4,-1) 7(1.4,-0.5) 8(1.4,0) 9(1.4,0.5) 10(1.4,1)
  rect 1.7x2.15 smd paste-1: 11(0,0)
  Top Layer L1 region: -0.7,-1.5 -0.5,-1.5 -0.5,-1.06 -0.7,-1.06
  Top Layer L1 region: -0.3,-1.5 -0.1,-1.5 -0.1,-1.06 -0.3,-1.06
  Top Layer L1 region: 0.3,-1.06 0.1,-1.06 0.1,-1.5 0.3,-1.5
  Top Layer L1 region: 0.7,-1.06 0.5,-1.06 0.5,-1.5 0.7,-1.5
  Top Layer L1 region: 0.7,1.5 0.5,1.5 0.5,1.06 0.7,1.06
  Top Layer L1 region: 0.3,1.5 0.1,1.5 0.1,1.06 0.3,1.06
  Top Layer L1 region: -0.3,1.06 -0.1,1.06 -0.1,1.5 -0.3,1.5
  Top Layer L1 region: -0.7,1.06 -0.5,1.06 -0.5,1.5 -0.7,1.5
  silkscreen extent -1.7,-1.7 1.7,1.7, body extent -1.58,-1.58 1.58,1.58, height 0.81
ESD_Overlay_Small [mil]
  silkscreen extent -62,-48 64,61
FCC_disclaimer [mil]
Fiducial10-30 [mm]
  round 1 smd mask+1: 1(0,0)
  Top Layer L1 keep-out circle w1.678: c0,0 r0.75
FIL_NFM41P [mm] "FILTER LC HIGH FREQ .2UF 1806"
  rect 1x1 smd: 1(-2.25,0) 3(2.25,0)
  rect 1.5x1 smd: 2(0,0.8) 2(0,-0.8)
  silkscreen extent -2.45,-1 2.45,1, body extent -2.4,-0.95 2.4,0.95, height 1.2
IEC_HotSurface_Small [mil]
  silkscreen extent -107,-93 107,92
IND_TDK_ACM7060 [mm] "TDK Common Mode EMI Filter 7mmx6mm"
  rect 2.5x1.5 smd: 1(-3.25,1.5) 2(-3.25,-1.5) 3(3.25,-1.5) 4(3.25,1.5)
  silkscreen extent -4.8,-3.32 4.75,3.31, body extent -3.6,-3.12 3.6,3.07, height 3.55
Johnson_142-0701-80x_NoVias [mil] "Johnson Components recommended land pattern"
  rect 25x200 smd: 1(0,0)
  rect 95x200 smd: 2(-172.5,0) 3(172.5,0)
  rect 95x200 smd far side: 4(-172.5,0) 5(172.5,0)
  silkscreen extent -240,-120 240,100, body extent -190,-92 190,480, height 165
Johnson_142-0701-231 [mil] "Johnson Components recommended land pattern"
  round 95 hole 62: 1(0,0)
  round 100 hole 67: 2(100,100) 3(100,-100) 4(-100,-100) 5(-100,100)
  silkscreen extent -165,-165 165,165, body extent -156,-156 156,156, height 375
Keystone5011 [mil] "Keystone Multipurpose loops"
  round 87 hole 63: 1(0,0)
  silkscreen extent -70,-70 70,70, body extent -63,-63 63,62, height 319
Keystone_1902C [mil] "Hex Standoff, 4-40 threaded, nylon"
  round 1 on Mech4: 0(0,0)
  body extent -145,-126 146,126, height 501
LED_LTST-C170 [mm] "LITE-ON"
  rect 1.2x1.2 smd: 1(-1.05,0) 2(1.05,0)
  silkscreen extent -1.6,-1.1 3,1.1, body extent -1.05,-0.67 1.05,0.67, height 1.1
LED_LTST-C190 [mm] "Lite-On"
  rect 0.8x0.8 smd: 1(-0.75,0) 2(0.75,0)
  silkscreen extent -1.1,-0.8 1.8,0.8, body extent -0.85,-0.45 0.85,0.45, height 0.9
LQFP64_N [mm] "Thin QFP, 64-Leads, Body 10x10mm, Pitch 0.5mm, IPC Medium Density"
  oval 1.8x0.3 smd mask+0.049: 1(-5.55,3.75) 2(-5.55,3.25) 3(-5.55,2.75) 4(-5.55,2.25) 5(-5.55,1.75) 6(-5.55,1.25) 7(-5.55,0.75) 8(-5.55,0.25) 9(-5.55,-0.25) 10(-5.55,-0.75) 11(-5.55,-1.25) 12(-5.55,-1.75) 13(-5.55,-2.25) 14(-5.55,-2.75) 15(-5.55,-3.25) 16(-5.55,-3.75) 33(5.55,-3.75) 34(5.55,-3.25) 35(5.55,-2.75) 36(5.55,-2.25) 37(5.55,-1.75) 38(5.55,-1.25) 39(5.55,-0.75) 40(5.55,-0.25) 41(5.55,0.25) 42(5.55,0.75) 43(5.55,1.25) 44(5.55,1.75) 45(5.55,2.25) 46(5.55,2.75) 47(5.55,3.25) 48(5.55,3.75)
  oval 0.3x1.8 smd mask+0.049: 17(-3.75,-5.55) 18(-3.25,-5.55) 19(-2.75,-5.55) 20(-2.25,-5.55) 21(-1.75,-5.55) 22(-1.25,-5.55) 23(-0.75,-5.55) 24(-0.25,-5.55) 25(0.25,-5.55) 26(0.75,-5.55) 27(1.25,-5.55) 28(1.75,-5.55) 29(2.25,-5.55) 30(2.75,-5.55) 31(3.25,-5.55) 32(3.75,-5.55) 49(3.75,5.55) 50(3.25,5.55) 51(2.75,5.55) 52(2.25,5.55) 53(1.75,5.55) 54(1.25,5.55) 55(0.75,5.55) 56(0.25,5.55) 57(-0.25,5.55) 58(-0.75,5.55) 59(-1.25,5.55) 60(-1.75,5.55) 61(-2.25,5.55) 62(-2.75,5.55) 63(-3.25,5.55) 64(-3.75,5.55)
  silkscreen extent -5.67,-4.25 4.25,4.57, body extent -5,-5 5,5, height 1.6
LQW18A [mm] "Murata"
  rect 0.625x0.85 smd: 1(-0.663,0) 2(0.663,0)
  silkscreen extent -0.13,-0.5 0.13,0.5, body extent -0.9,-0.5 0.9,0.5, height 1
M08A_L [mm] "SOIC, 8-Leads, Body 4.9x3.9mm, Pitch 1.27mm, IPC High Density"
  oval 1.9x0.6 smd: 1(-2.35,1.905) 2(-2.35,0.635) 3(-2.35,-0.635) 4(-2.35,-1.905) 5(2.35,-1.905) 6(2.35,-0.635) 7(2.35,0.635) 8(2.35,1.905)
  silkscreen extent -2.47,-2.5 1,2.88, body extent -2,-2.5 2,2.5, height 1.75
Mini-Circuits-DB1627 [mm] "Mini-Circuits DB1627 Footprint"
  rect 0.76x1.65 smd: 1(-1.27,1.59) 2(0,1.59) 3(1.27,1.59) 4(1.27,-1.59) 5(0,-1.59) 6(-1.27,-1.59)
  silkscreen extent -3.01,-2.03 1.91,2.03, body extent -1.91,-2.03 1.91,2.03, height 4.07
MRA08A_N [mm] "SOIC, 8-Leads, Body 4.9x3.9mm, Pitch 1.27mm, Exposed Pad, IPC Medium Density"
  oval 2x0.6 smd: 1(-2.5,1.905) 2(-2.5,0.635) 3(-2.5,-0.635) 4(-2.5,-1.905) 5(2.5,-1.905) 6(2.5,-0.635) 7(2.5,0.635) 8(2.5,1.905)
  rect 2.29x2.29 smd: 9(0,0)
  silkscreen extent -2.63,-2.5 1.1,2.88, body extent -2,-2.5 2,2.5, height 1.68
MSOP-MS8_N [mm] "TSOP, 8-Leads, Body 3x3mm, Pitch 0.65mm, IPC Medium Density"
  oval 1.7x0.45 smd mask+0.049: 1(-2.1,0.975) 2(-2.1,0.325) 3(-2.1,-0.325) 4(-2.1,-0.975) 5(2.1,-0.975) 6(2.1,-0.325) 7(2.1,0.325) 8(2.1,0.975)
  silkscreen extent -2.22,-1.55 0.85,1.87, body extent -1.6,-1.6 1.6,1.6, height 1.1
MSS1038 [mil]
  rect 80x140 smd: 1(-185,0) 2(185,0)
  silkscreen extent -216,-208 215,208, body extent -203,-201 203,201, height 158
MUA08A_N [mm] "TSOP, 8-Leads, Body 3x3mm, Pitch 0.65mm, IPC Medium Density"
  oval 1.7x0.45 smd mask+0.049: 1(-2.1,0.975) 2(-2.1,0.325) 3(-2.1,-0.325) 4(-2.1,-0.975) 5(2.1,-0.975) 6(2.1,-0.325) 7(2.1,0.325) 8(2.1,0.975)
  silkscreen extent -2.22,-1.55 0.85,1.87, body extent -1.6,-1.6 1.6,1.6, height 1.09
NKD0064A [mm] "QFN, 64-Leads, Body 9x9mm, Pitch 0.5mm"
  rect 0.6x0.25 smd mask+0.051: 1(-4.4,3.75) 2(-4.4,3.25) 3(-4.4,2.75) 4(-4.4,2.25) 5(-4.4,1.75) 6(-4.4,1.25) 7(-4.4,0.75) 8(-4.4,0.25) 9(-4.4,-0.25) 10(-4.4,-0.75) 11(-4.4,-1.25) 12(-4.4,-1.75) 13(-4.4,-2.25) 14(-4.4,-2.75) 15(-4.4,-3.25) 16(-4.4,-3.75) 33(4.4,-3.75) 34(4.4,-3.25) 35(4.4,-2.75) 36(4.4,-2.25) 37(4.4,-1.75) 38(4.4,-1.25) 39(4.4,-0.75) 40(4.4,-0.25) 41(4.4,0.25) 42(4.4,0.75) 43(4.4,1.25) 44(4.4,1.75) 45(4.4,2.25) 46(4.4,2.75) 47(4.4,3.25) 48(4.4,3.75)
  rect 0.25x0.6 smd mask+0.051: 17(-3.75,-4.4) 18(-3.25,-4.4) 19(-2.75,-4.4) 20(-2.25,-4.4) 21(-1.75,-4.4) 22(-1.25,-4.4) 23(-0.75,-4.4) 24(-0.25,-4.4) 25(0.25,-4.4) 26(0.75,-4.4) 27(1.25,-4.4) 28(1.75,-4.4) 29(2.25,-4.4) 30(2.75,-4.4) 31(3.25,-4.4) 32(3.75,-4.4) 49(3.75,4.4) 50(3.25,4.4) 51(2.75,4.4) 52(2.25,4.4) 53(1.75,4.4) 54(1.25,4.4) 55(0.75,4.4) 56(0.25,4.4) 57(-0.25,4.4) 58(-0.75,4.4) 59(-1.25,4.4) 60(-1.75,4.4) 61(-2.25,4.4) 62(-2.75,4.4) 63(-3.25,4.4) 64(-3.75,4.4)
  rect 7.2x7.2 smd paste-3.6 mask+0.051: 65(0,0)
  silkscreen extent -5.52,-4.85 4.85,4.85, body extent -4.55,-4.55 4.55,4.55, height 0.8
"NY PMS 440 0025 PH"#1 [mm] "4-40 nylon screw and mounting hole"
  round 8 / inner round 4.216 / far side round 8 hole 3.2 mask+0.037: 1(0,0)
  body extent -3.3,-3.3 3.3,3.3, height 2.69
"NY PMS 440 0025 PH"#2 [mm] "4-40 nylon screw and mounting hole"
  round 8 / inner round 4.216 / far side round 8 hole 3.2: 1(0,0)
  body extent -3.3,-3.3 3.3,3.3, height 2.69
OSC_CWX [mm] "CONNOR WINFIELD"
  rect 2x1.8 smd: 1(-2.1,2.54) 2(-2.1,-2.54) 3(2.1,-2.54) 4(2.1,2.54)
  silkscreen extent -2.7,-3.7 2.7,4.55, body extent -2.65,-3.65 2.65,3.65, height 1.31
Pb-Free_Overlay_Small [mil]
  silkscreen extent -46,-46 46,46
PBC03SAAN [mm] "Sullins 100mil, 1x3, 230 mil above insulator"
  rect 1.65x1.65 hole 1.016: 1(-2.54,0)
  round 1.65 hole 1.016: 2(0,0) 3(2.54,0)
  silkscreen extent -3.81,-1.27 3.81,1.27, body extent -3.81,-1.27 3.81,1.27, height 8.38
PW0014A_N [mm] "TSOP, 14-Leads, Body 5x4.4mm, Pitch 0.65mm, IPC Medium Density"
  oval 1.4x0.45 smd mask+0.049: 1(-2.95,1.95) 2(-2.95,1.3) 3(-2.95,0.65) 4(-2.95,0) 5(-2.95,-0.65) 6(-2.95,-1.3) 7(-2.95,-1.95) 8(2.95,-1.95) 9(2.95,-1.3) 10(2.95,-0.65) 11(2.95,0) 12(2.95,0.65) 13(2.95,1.3) 14(2.95,1.95)
  silkscreen extent -3.4,-2.55 1.85,2.55, body extent -3.21,-2.5 3.21,2.5, height 1
PW0016A_L [mm] "TSOP, 16-Leads, Body 5x4.4mm, Pitch 0.65mm, IPC High Density"
  oval 1.4x0.35 smd: 1(-2.8,2.275) 2(-2.8,1.625) 3(-2.8,0.975) 4(-2.8,0.325) 5(-2.8,-0.325) 6(-2.8,-0.975) 7(-2.8,-1.625) 8(-2.8,-2.275) 9(2.8,-2.275) 10(2.8,-1.625) 11(2.8,-0.975) 12(2.8,-0.325) 13(2.8,0.325) 14(2.8,0.975) 15(2.8,1.625) 16(2.8,2.275)
  silkscreen extent -2.92,-2.55 1.7,3.12, body extent -2.25,-2.55 2.25,2.55, height 1.2
PW0016A_N [mm] "TSOP, 16-Leads, Body 5x4.4mm, Pitch 0.65mm, IPC Medium Density"
  oval 1.4x0.45 smd mask+0.049: 1(-2.95,2.275) 2(-2.95,1.625) 3(-2.95,0.975) 4(-2.95,0.325) 5(-2.95,-0.325) 6(-2.95,-0.975) 7(-2.95,-1.625) 8(-2.95,-2.275) 9(2.95,-2.275) 10(2.95,-1.625) 11(2.95,-0.975) 12(2.95,-0.325) 13(2.95,0.325) 14(2.95,0.975) 15(2.95,1.625) 16(2.95,2.275)
  silkscreen extent -3.5,-2.55 1.85,2.75, body extent -3.21,-2.5 3.21,2.5, height 1
RELAY_DS1E-SL2 [mm] "TH, 6-Leads, Body 15x9.9mm"
  rect 1.4x1.4 hole 0.9: 1(-3.81,6.35)
  round 1.4 hole 0.9: 3(-3.81,1.27) 6(-3.81,-6.35) 7(3.81,-6.35) 10(3.81,1.27) 12(3.81,6.35)
  silkscreen extent -5.5,-7.49 4.95,7.49, body extent -4.95,-7.49 4.95,7.49, height 10.2
Relay_RF180 [mm] "TH, 10-Leads, Body 9.53x12.06mm"
  rect 1.25x1.25 hole 0.75: 1(-2.54,3.81)
  round 1.25 hole 0.75: 2(-2.54,1.27) 3(-2.54,-1.27) 4(-2.54,-3.81) 6(2.54,-3.81) 7(2.54,-1.27) 8(2.54,1.27) 9(2.54,3.81)
  round 1.25 hole 0.75 paste+0: 5(0,-3.81) 10(0,3.81)
  silkscreen extent -4.76,-6.03 4.76,6.92, body extent -4.76,-6.03 4.76,6.92, height 8.25
RGW0020A [mm] "QFN, 20-Leads, Body 5x5mm, Pitch 0.65mm, Thermal Pad 3.15x3.15mm, TI Recommended"
  oval 1x0.35 smd paste-0.025 mask+0.07: 1(-2.4,1.3) 2(-2.4,0.65) 3(-2.4,0) 4(-2.4,-0.65) 5(-2.4,-1.3) 11(2.4,-1.3) 12(2.4,-0.65) 13(2.4,0) 14(2.4,0.65) 15(2.4,1.3)
  oval 0.35x1 smd paste-0.025 mask+0.07: 6(-1.3,-2.4) 7(-0.65,-2.4) 8(0,-2.4) 9(0.65,-2.4) 10(1.3,-2.4) 16(1.3,2.4) 17(0.65,2.4) 18(0,2.4) 19(-0.65,2.4) 20(-1.3,2.4)
  rect 3.15x3.15 smd paste-1.575 mask+0.07: 21(0,0)
  silkscreen extent -3.5,-2.73 2.73,2.73, body extent -2.58,-2.57 2.57,2.58, height 1
RHB0032E [mm] "QFN, 32-Leads, Body 5x5mm, Pitch 0.5mm, Thermal Pad 3.45x3.45mm, TI Recommended"
  oval 0.6x0.24 smd mask+0.07: 1(-2.4,1.75) 2(-2.4,1.25) 3(-2.4,0.75) 4(-2.4,0.25) 5(-2.4,-0.25) 6(-2.4,-0.75) 7(-2.4,-1.25) 8(-2.4,-1.75) 17(2.4,-1.75) 18(2.4,-1.25) 19(2.4,-0.75) 20(2.4,-0.25) 21(2.4,0.25) 22(2.4,0.75) 23(2.4,1.25) 24(2.4,1.75)
  oval 0.24x0.6 smd mask+0.07: 9(-1.75,-2.4) 10(-1.25,-2.4) 11(-0.75,-2.4) 12(-0.25,-2.4) 13(0.25,-2.4) 14(0.75,-2.4) 15(1.25,-2.4) 16(1.75,-2.4) 25(1.75,2.4) 26(1.25,2.4) 27(0.75,2.4) 28(0.25,2.4) 29(-0.25,2.4) 30(-0.75,2.4) 31(-1.25,2.4) 32(-1.75,2.4)
  rect 3.45x3.45 smd paste-1.725 mask+0.07: 33(0,0)
  silkscreen extent -2.72,2.29 -2.29,2.73, body extent -2.57,-2.57 2.58,2.58, height 1.01
RLY0068A [mm] "QFN, 68-Leads, Body 10x10mm, Pitch 0.5mm"
  rect 0.6x0.25 smd mask+0.051: 1(-4.9,4) 2(-4.9,3.5) 3(-4.9,3) 4(-4.9,2.5) 5(-4.9,2) 6(-4.9,1.5) 7(-4.9,1) 8(-4.9,0.5) 9(-4.9,0) 10(-4.9,-0.5) 11(-4.9,-1) 12(-4.9,-1.5) 13(-4.9,-2) 14(-4.9,-2.5) 15(-4.9,-3) 16(-4.9,-3.5) 17(-4.9,-4) 35(4.9,-4) 36(4.9,-3.5) 37(4.9,-3) 38(4.9,-2.5) 39(4.9,-2) 40(4.9,-1.5) 41(4.9,-1) 42(4.9,-0.5) 43(4.9,0) 44(4.9,0.5) 45(4.9,1) 46(4.9,1.5) 47(4.9,2) 48(4.9,2.5) 49(4.9,3) 50(4.9,3.5) 51(4.9,4)
  rect 0.25x0.6 smd mask+0.051: 18(-4,-4.9) 19(-3.5,-4.9) 20(-3,-4.9) 21(-2.5,-4.9) 22(-2,-4.9) 23(-1.5,-4.9) 24(-1,-4.9) 25(-0.5,-4.9) 26(0,-4.9) 27(0.5,-4.9) 28(1,-4.9) 29(1.5,-4.9) 30(2,-4.9) 31(2.5,-4.9) 32(3,-4.9) 33(3.5,-4.9) 34(4,-4.9) 52(4,4.9) 53(3.5,4.9) 54(3,4.9) 55(2.5,4.9) 56(2,4.9) 57(1.5,4.9) 58(1,4.9) 59(0.5,4.9) 60(0,4.9) 61(-0.5,4.9) 62(-1,4.9) 63(-1.5,4.9) 64(-2,4.9) 65(-2.5,4.9) 66(-3,4.9) 67(-3.5,4.9) 68(-4,4.9)
  rect 8.1x8.1 smd paste-4.05 mask+0.051: 69(0,0)
  silkscreen extent -5.87,-5.2 5.2,5.2, body extent -5.05,-5.05 5.05,5.05, height 1.01
RMS0014A [mm] "QFN, Body 2.6x2.6mm, Pitch 0.5mm"
  oval 0.7x0.25 smd: 1(-1.1,0.5)
  oval 0.6x0.25 smd: 2(-1.15,0) 3(-1.15,-0.5) 8(1.15,-0.5) 9(1.15,0) 10(1.15,0.5)
  oval 0.25x0.6 smd: 4(-0.75,-1.15) 5(-0.25,-1.15) 6(0.25,-1.15) 7(0.75,-1.15) 11(0.75,1.15) 12(0.25,1.15) 13(-0.25,1.15) 14(-0.75,1.15)
  silkscreen extent -1.4,-1.4 1.4,1.4, body extent -1.3,-1.3 1.3,1.3, height 0.61
RMZ0016A [mm] "QFN, 16-Leads, Body 3.0x3.0 mm, Pitch 0.5mm"
  rrect40% 0.8x0.25 smd paste+0 mask+0.07: 1(-1.3,0.75)
  rrect40% 0.6x0.25 smd paste+0 mask+0.07: 2(-1.4,0.25) 3(-1.4,-0.25) 4(-1.4,-0.75) 9(1.4,-0.75) 10(1.4,-0.25) 11(1.4,0.25) 12(1.4,0.75)
  rrect40% 0.25x0.6 smd paste+0 mask+0.07: 5(-0.75,-1.4) 6(-0.25,-1.4) 7(0.25,-1.4) 8(0.75,-1.4) 13(0.75,1.4) 14(0.25,1.4) 15(-0.25,1.4) 16(-0.75,1.4)
  rrect40% 0.25x0.25 smd paste+0 mask+0.07: ""(-1.25,-1.25) ""(-1.25,1.25) ""(1.25,-1.25) ""(1.25,1.25)
  silkscreen extent -1.7,-1.7 1.7,1.7, body extent -1.55,-1.55 1.55,1.55, height 0.66
SDA14B [mm] "SON, 14-Leads, Body 4x4mm, Pitch 0.5mm, NSC Recommended"
  rect 0.6x0.25 smd paste-0.125 mask+0.051: 1(-1.9,1.5) 2(-1.9,1) 3(-1.9,0.5) 4(-1.9,0) 5(-1.9,-0.5) 6(-1.9,-1) 7(-1.9,-1.5) 8(1.9,-1.5) 9(1.9,-1) 10(1.9,-0.5) 11(1.9,0) 12(1.9,0.5) 13(1.9,1) 14(1.9,1.5)
  rect 2.6x3 smd paste-1.3 mask+0.051: 15(0,0)
  silkscreen extent -2.82,-2.2 2.35,2.87, body extent -2.05,-2.05 2.05,2.05, height 0.8
SDA16A [mm] "SON, 16-Leads, Body 5x5mm, Pitch 0.5mm, NSC Recommended"
  rect 0.6x0.25 smd paste-0.125 mask+0.051: 1(-2.4,1.75) 2(-2.4,1.25) 3(-2.4,0.75) 4(-2.4,0.25) 5(-2.4,-0.25) 6(-2.4,-0.75) 7(-2.4,-1.25) 8(-2.4,-1.75) 9(2.4,-1.75) 10(2.4,-1.25) 11(2.4,-0.75) 12(2.4,-0.25) 13(2.4,0.25) 14(2.4,0.75) 15(2.4,1.25) 16(2.4,1.75)
  rect 3.6x4 smd paste-1.8 mask+0.051: 17(0,0)
  silkscreen extent -2.85,-2.7 2.85,3.53, body extent -2.55,-2.55 2.55,2.55, height 0.8
SMC [mil] "Molded Diode, 2-Leads, Body 6.9x5.8mm, IPC Medium Density, based on OnSemi component dimensions and land patterns"
  rect 110x150 smd: 1(-140.49,0) 2(140.49,0)
  silkscreen extent -221,-124 189,124, body extent -156,-116 156,116, height 91
SNT-100-BK-G [mil] "Samtec STEP model"
  round 1 on Mech3: 0(0,0)
  body extent -100,-50 100,50, height 344
SOD882 [mm] "NXP Semiconductor"
  rect 0.4x0.7 smd paste-0.05: 1(-0.35,0) 2(0.35,0)
  silkscreen extent -0.95,-0.35 -0.72,0.35, body extent -0.51,-0.31 0.51,0.31, height 0.51
SOD-123 [mm] "On Semi recommended land pattern"
  rect 0.915x1.22 smd: 1(-1.637,0) 2(1.637,0)
  silkscreen extent -2.74,-1.17 2.03,1.17, body extent -1.93,-0.9 1.93,0.9, height 1.35
SOIJ-SM8_N [mm] "SOP, 8-Leads, Body 5.2x5.2mm, Pitch 1.27mm, IPC Medium Density"
  oval 2.2x0.6 smd: 1(-3.4,1.905) 2(-3.4,0.635) 3(-3.4,-0.635) 4(-3.4,-1.905) 5(3.4,-1.905) 6(3.4,-0.635) 7(3.4,0.635) 8(3.4,1.905)
  silkscreen extent -3.52,-2.75 1.9,2.88, body extent -2.73,-2.75 2.73,2.75, height 2.04
SOP-5_.95MM_(DBV) [mil]
  rect 42x25 smd: 1(-48.94,37.39) 2(-48.94,0) 3(-48.94,-37.39) 4(45.94,-37.39) 5(45.94,37.39)
  silkscreen extent -115,27 -90,52
SOT-23 [mil]
  rect 35x35 smd: 1(-37.5,-52.5) 2(37.5,-52.5) 3(0,50)
SOT-563 [mil] "Vishay recommended land pattern document 72605.pdf"
  rect 19x12 smd mask+2: 1(-25,20) 2(-25,0) 3(-25,-20) 4(25,-20) 5(25,0) 6(25,20)
  silkscreen extent -44,32 -44,32, body extent -33,-33 33,33, height 24
"SW_ L101011MS02Q" [mm] "SWITCH SLIDE sPST 4A PCB"
  rect 2.416x2.416 hole 1.65: 1(2.855,4.6)
  round 2.416 hole 1.65: 2(2.855,0) 3(2.855,-4.6)
  silkscreen extent -5.4,-9.55 5.4,9.55, body extent -5.39,-9.55 5.39,9.55, height 14.18
SW_RS-032G05A3-SM [mm] "SMT, 2-Leads, Body 6x3.5mm, Pin Spacing 8mm"
  rect 2x2 smd: 1(-4,0) 2(4,0)
  silkscreen extent -3,-1.75 3,1.75, body extent -4,-1.75 4,1.75, height 4.3
TESTPOINT#1 [mil]
  round 80 hole 37.99: 1(0,0)
TESTPOINT#2 [mil]
  round 25.98 hole 12.99: 1(0,0)
TESTPOINT#3 [mil]
  round 25.98 hole 12.99: 1(0,23.68)
TI_Symbol_Overlay_Small [mil]
  silkscreen extent -90,-88 91,88
TJ5A_N [mm] "D2-PAK, 6-Leads, Body 9.9x10.2mm, Pitch 1.7mm, Lead Span 14mm, IPC Medium Density"
  rect 3.2x0.95 smd: 1(-6,3.4) 2(-6,1.7) 3(-6,0) 4(-6,-1.7) 5(-6,-3.4)
  rect 7.4x5.75 smd: 6(3.9,0)
  silkscreen extent -6.12,-5.2 -0.2,5.2, body extent -1.95,-5.2 8.15,5.2, height 2.1
TP_VIA_060RND040 [mil] "TP_VIA_060RND040"
  round 60 hole 40: 1(0,0)
TRANS_NexFET_Q5B [mm] "TI recommended land pattern (nominal) November 2012"
  rect 1.372x0.71 smd paste-0.4: 1(-3.437,1.768) 2(-3.437,0.498) 3(-3.437,-0.772) 4(-3.437,-2.042)
  rect 0.59x0.71 smd paste-0.3: 5(2.116,-2.042) 6(2.116,-0.772) 7(2.116,0.498) 8(2.116,1.768)
  Top Layer L1 region: -1.767,-2.397 2.083,-2.397 2.083,2.123 -1.767,2.123
  silkscreen extent -4.05,-2.84 2.34,2.56, body extent -3.89,-2.69 2.21,2.41, height 1.06
TRIM_3214W [mm] "BOURNS"
  rect 1.6x1.3 smd: 1(-1.45,1.25) 3(-1.45,-1.25)
  rect 1.6x2 smd: 2(1.45,0)
  silkscreen extent -1.9,-2.55 1.9,2.55, body extent -1.87,-2.52 1.87,2.52, height 5.56
TSW-102-07-G-S [mm] "Samtec 100mil, 1x2, 230 mil above insulator"
  rect 1.65x1.65 hole 1.016 mask+0: 1(-1.27,0)
  round 1.65 hole 1.016 mask+0: 2(1.27,0)
  silkscreen extent -3.56,-1.27 2.54,1.27, body extent -2.54,-1.27 2.54,1.27, height 8.38
TSW-103-07-G-D [mm] "Samtec 100mil, 2x3, 230 mil above insulator"
  rect 1.65x1.65 hole 1.016 mask+0: 1(-2.54,-1.27)
  round 1.65 hole 1.016 mask+0: 2(-2.54,1.27) 3(0,-1.27) 4(0,1.27) 5(2.54,-1.27) 6(2.54,1.27)
  silkscreen extent -4.83,-2.54 3.81,2.54, body extent -3.81,-2.54 3.81,2.54, height 8.38
TSW-103-07-G-S [mm] "Samtec 100mil, 1x3, 230 mil above insulator"
  rect 1.65x1.65 hole 1.016 mask+0: 1(-2.54,0)
  round 1.65 hole 1.016 mask+0: 2(0,0) 3(2.54,0)
  silkscreen extent -4.84,-1.27 3.81,1.27, body extent -3.81,-1.27 3.81,1.27, height 8.38
TSW-104-07-G-D [mm] "Samtec 100mil, 2x4, 230 mil above insulator"
  rect 1.65x1.65 hole 1.016 mask+0: 1(-3.81,-1.27)
  round 1.65 hole 1.016 mask+0: 2(-3.81,1.27) 3(-1.27,-1.27) 4(-1.27,1.27) 5(1.27,-1.27) 6(1.27,1.27) 7(3.81,-1.27) 8(3.81,1.27)
  silkscreen extent -6.1,-2.54 5.08,2.54, body extent -5.08,-2.54 5.08,2.54, height 8.38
